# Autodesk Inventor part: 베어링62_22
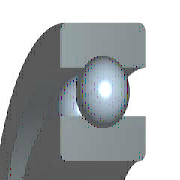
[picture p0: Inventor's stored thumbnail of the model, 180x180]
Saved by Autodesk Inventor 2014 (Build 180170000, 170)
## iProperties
Created: 2009-02
Part Number: 베어링62_22
Material: 강, 연강
Description: 깊은 그루브 볼 베어링
Document SubType Name: Modeling
Standard: KS B 2023
Designer: KYOUNG IL JANG
Standards Organization: KS
Language: ko-KR
Size Designation: 62/22 - 22 x 50 x 14
Categories: <MemberInstance><Categories><Category DisplayName="샤프트 부품" InternalName="7f7aeb1f-a693-4053-b835-cee3144e0d98" Mnemonic="SHFT"><Category DisplayName="베어링" Inter
Density: 1 g/cm^3
Appearance: 강철
IsCustomPart: 0
Author: KYOUNG IL JANG
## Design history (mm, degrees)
sketch "스케치" dims "d0" = 7.28 (= -0.26 x WD + 0.26 x BD)
  geometry: L1 (3.36, 18)-(10.64, 18); L2 (7, 18)-(7, 14.36); L3 (7, 18)-(7, 21.64); L4 (4.295, 15.564)-(0, 15.564); L5 (0, 11)-(14, 11); L6 (4.295, 20.436)-(0, 20.436); L7 (0, 25)-(14, 25); L8 (14, 11)-(14, 15.564); L9 (9.705, 15.564)-(14, 15.564); L10 (9.705, 20.436)-(14, 20.436); L11 (14, 25)-(14, 20.436); L12 (-1.4, 0)-(8.4, 0) reference; L13 (0, -0.3)-(0, 5.3) reference
  constraints: 22 end point, 4 point on line, 2 collinear, 2 perpendicular, 2 symmetric about line, 1 midpoint, 1 parallel, 14 other
  dimensions: "d9" = 22 diameter of L5 L12 (= WD); "d11" = 50 diameter of L7 L12 (= BD); "d12" = 14 distance between parallel lines of L8 L13 (= KB); "d13" = 31.128 diameter of L9 L12 (= 0.326 x BD + 0.674 x WD)
revolve "본체" stored, may be unused: angle "d6" = 90 deg
revolve "볼" stored, may be unused: angle "d7" = 90 deg
pattern_circular "IDS_ARRAYBALL[SIMPL:T]" dims angle "d3" = 360 deg
body "Solid1"
fillet "모깎기1" dims "d1" = 1 (= KRS)
other parameters: "WD" = 22 [user parameter; used in 5 equation terms], "BD" = 50 [user parameter; used in 5 equation terms], "KB" = 14 [user parameter; used in 1 equation term], "KRS" = 1 [user parameter; used in 1 equation term], "d4" = 0, "d5" = 0, "d8" = 0, "d14" = 0, "d15" = 0, "BBA" = 0 [user parameter], "BC0" = 7154000 [user parameter], "BC" = 1.2233e+07 [user parameter], "BR" = 25 (= 0.5 x BD) [user parameter], "WR" = 11 (= 0.5 x WD) [user parameter]
